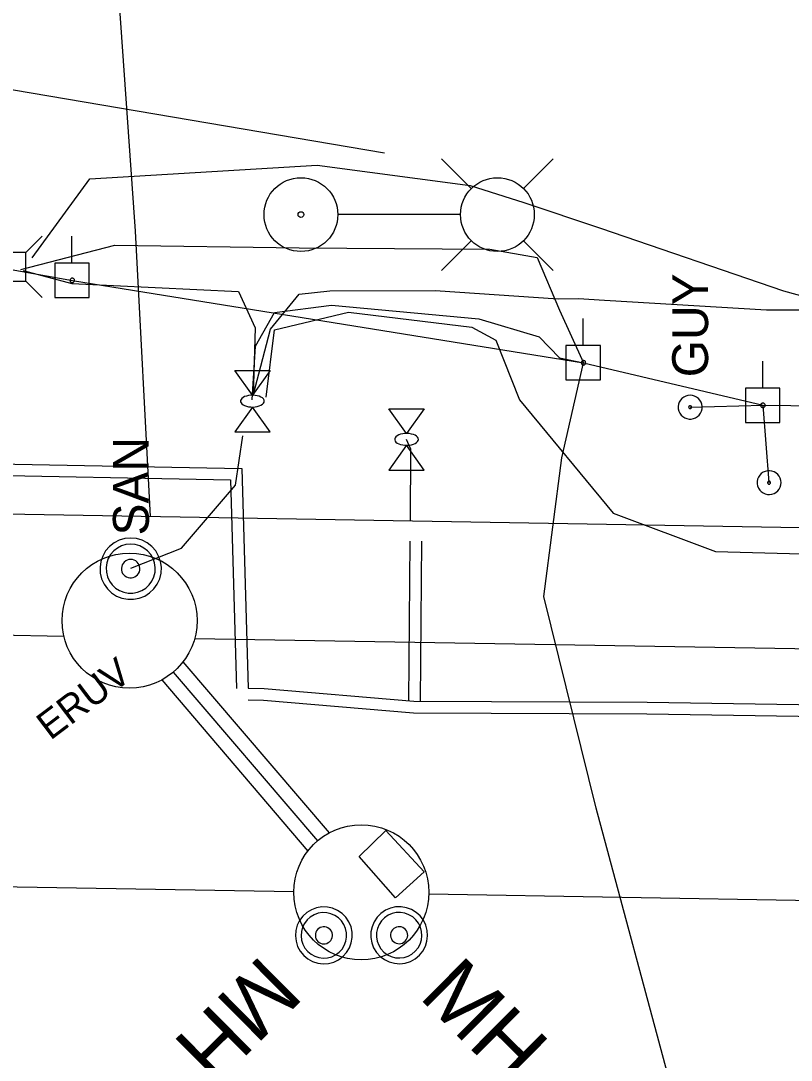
# Model space of a CAD drawing. Extents: x 596028 to 606371, y 330010 to 403088.
# Drawn here: x 604635.9 to 604718.6, y 337984.6 to 338096.2 of the extents above; entities that cross this region are included whole.
import ezdxf

# ---------------------------------------------------------------- set-up
doc = ezdxf.new("R2010")
doc.units = 0
for name, color, linetype in [('E_LTG', 7, 'Continuous'), ('E_UTL_E_Bold', 7, 'Continuous'), ('E_UTL_E_UG', 7, 'Continuous'), ('E_UTL_EGuyWire', 7, 'Continuous'), ('E_UTL_EPowerPole', 7, 'Continuous'), ('E_UTL_G_UG', 7, 'Continuous'), ('E_UTL_Overhead', 7, 'Continuous'), ('E_UTL_SAN', 7, 'Continuous'), ('E_UTL_SAN_MH', 7, 'Continuous'), ('E_UTL_SAN_UG_MMSD', 7, 'Continuous'), ('E_UTL_SAN_UG_OUTER_LIMITS', 7, 'Continuous'), ('E_UTL_T', 7, 'Continuous'), ('E_UTL_T_UG', 7, 'Continuous'), ('E_UTL_TV_UG', 7, 'Continuous')]:
    doc.layers.add(name, color=color, linetype=linetype)

# ---------------------------------------------------------------- blocks, each defined once
blk = doc.blocks.new('ACAD_PROXY_ENTITY_20')
at = {"layer": 'E_UTL_SAN'}
for points in [[(1843060.22, 1030211.23), (1843061.35, 1030212.59), (1843062.2, 1030214.15), (1843062.74, 1030215.83), (1843062.95, 1030217.59), (1843062.82, 1030219.36), (1843062.36, 1030221.07), (1843061.59, 1030222.66), (1843060.53, 1030224.08), (1843059.22, 1030225.27), (1843057.71, 1030226.19), (1843056.05, 1030226.81), (1843054.3, 1030227.1), (1843052.53, 1030227.06), (1843050.8, 1030226.68), (1843049.17, 1030225.99), (1843047.71, 1030224.99), (1843046.45, 1030223.74), (1843045.46, 1030222.28), (1843044.77, 1030220.65), (1843044.39, 1030218.92), (1843044.35, 1030217.15), (1843044.64, 1030215.4), (1843045.26, 1030213.74), (1843046.18, 1030212.23), (1843047.37, 1030210.92), (1843048.79, 1030209.86), (1843050.38, 1030209.09), (1843052.09, 1030208.63), (1843053.86, 1030208.5), (1843055.62, 1030208.71), (1843057.3, 1030209.25), (1843058.86, 1030210.1), (1843060.22, 1030211.23)], [(1843058.9, 1030212.54), (1843059.81, 1030213.64), (1843060.49, 1030214.88), (1843060.92, 1030216.23), (1843061.08, 1030217.63), (1843060.98, 1030219.05), (1843060.62, 1030220.42), (1843060, 1030221.69), (1843059.15, 1030222.82), (1843058.1, 1030223.78), (1843056.89, 1030224.51), (1843055.56, 1030225.01), (1843054.17, 1030225.24), (1843052.75, 1030225.21), (1843051.37, 1030224.91), (1843050.07, 1030224.35), (1843048.89, 1030223.56), (1843047.89, 1030222.56), (1843047.1, 1030221.38), (1843046.54, 1030220.08), (1843046.24, 1030218.7), (1843046.2, 1030217.28), (1843046.44, 1030215.88), (1843046.93, 1030214.56), (1843047.67, 1030213.35), (1843048.62, 1030212.3), (1843049.76, 1030211.45), (1843051.03, 1030210.83), (1843052.4, 1030210.46), (1843053.81, 1030210.36), (1843055.22, 1030210.53), (1843056.57, 1030210.96), (1843057.81, 1030211.64), (1843058.9, 1030212.54)], [(1843055.61, 1030215.84), (1843055.95, 1030216.25), (1843056.2, 1030216.71), (1843056.37, 1030217.22), (1843056.43, 1030217.75), (1843056.39, 1030218.28), (1843056.25, 1030218.79), (1843056.02, 1030219.27), (1843055.7, 1030219.69), (1843055.31, 1030220.05), (1843054.86, 1030220.33), (1843054.36, 1030220.51), (1843053.84, 1030220.6), (1843053.3, 1030220.59), (1843052.79, 1030220.47), (1843052.3, 1030220.26), (1843051.86, 1030219.97), (1843051.48, 1030219.59), (1843051.18, 1030219.15), (1843050.97, 1030218.66), (1843050.86, 1030218.14), (1843050.85, 1030217.61), (1843050.94, 1030217.09), (1843051.12, 1030216.59), (1843051.4, 1030216.14), (1843051.76, 1030215.74), (1843052.18, 1030215.43), (1843052.66, 1030215.19), (1843053.17, 1030215.06), (1843053.7, 1030215.02), (1843054.23, 1030215.08), (1843054.74, 1030215.24), (1843055.2, 1030215.5), (1843055.61, 1030215.84)]]:
    blk.add_lwpolyline(points, dxfattribs=at)
blk.add_text('MH', height=20.117, rotation=315, dxfattribs=at).set_placement((1843059.69, 1030197.53))

msp = doc.modelspace()

# ---------------------------------------------------------------- linework, layer by layer
at = {"layer": 'E_LTG'}
for points in [[(604684.27, 338078.14), (604681.04, 338081.36)], [(604689.81, 338078.14), (604693.04, 338081.36)], [(604683.02, 338075.36), (604669.97, 338075.36)], [(604684.27, 338072.59), (604681.04, 338069.36)], [(604689.81, 338072.59), (604693.04, 338069.36)]]:
    msp.add_lwpolyline(points, dxfattribs=at)
for centre, radius in [((604665.94, 338075.36), 3.96), ((604687.04, 338075.36), 3.96), ((604665.94, 338075.36), 0.303)]:
    msp.add_circle(centre, radius, dxfattribs=at)
at = {"layer": 'E_UTL_E_Bold'}
for points in [[(604658.83, 338058.63), (604662.64, 338058.63)], [(604660.73, 338055.97), (604658.83, 338058.63)], [(604662.64, 338058.63), (604660.73, 338055.97)], [(604662, 338055.33), (604661.98, 338055.45), (604661.91, 338055.57), (604661.8, 338055.68), (604661.65, 338055.77), (604661.47, 338055.85), (604661.26, 338055.91), (604661.03, 338055.95), (604660.79, 338055.97), (604660.55, 338055.96), (604660.32, 338055.93), (604660.1, 338055.88), (604659.9, 338055.81), (604659.73, 338055.73), (604659.6, 338055.62), (604659.51, 338055.51), (604659.47, 338055.39), (604659.47, 338055.27), (604659.51, 338055.15), (604659.6, 338055.04), (604659.73, 338054.94), (604659.9, 338054.85), (604660.1, 338054.78), (604660.32, 338054.73), (604660.55, 338054.71), (604660.79, 338054.7), (604661.03, 338054.72), (604661.26, 338054.76), (604661.47, 338054.82), (604661.65, 338054.9), (604661.8, 338054.99), (604661.91, 338055.1), (604661.98, 338055.21), (604662, 338055.33)], [(604660.73, 338054.7), (604658.83, 338052.03)], [(604662.64, 338052.03), (604660.73, 338054.7)], [(604675.38, 338054.52), (604679.19, 338054.52)], [(604677.28, 338051.86), (604675.38, 338054.52)], [(604679.19, 338054.52), (604677.28, 338051.86)], [(604658.83, 338052.03), (604662.64, 338052.03)], [(604678.55, 338051.22), (604678.53, 338051.34), (604678.46, 338051.46), (604678.35, 338051.57), (604678.2, 338051.66), (604678.02, 338051.74), (604677.81, 338051.8), (604677.58, 338051.84), (604677.34, 338051.86), (604677.1, 338051.85), (604676.87, 338051.82), (604676.65, 338051.77), (604676.45, 338051.7), (604676.28, 338051.62), (604676.15, 338051.51), (604676.06, 338051.4), (604676.02, 338051.28), (604676.02, 338051.16), (604676.06, 338051.04), (604676.15, 338050.93), (604676.28, 338050.83), (604676.45, 338050.74), (604676.65, 338050.67), (604676.87, 338050.62), (604677.1, 338050.6), (604677.34, 338050.59), (604677.58, 338050.61), (604677.81, 338050.65), (604678.02, 338050.71), (604678.2, 338050.79), (604678.35, 338050.88), (604678.46, 338050.99), (604678.53, 338051.1), (604678.55, 338051.22)], [(604677.28, 338050.59), (604675.38, 338047.92)], [(604679.19, 338047.92), (604677.28, 338050.59)], [(604675.38, 338047.92), (604679.19, 338047.92)]]:
    msp.add_lwpolyline(points, dxfattribs=at)
at = {"layer": 'E_UTL_E_UG'}
for points in [[(604660.72, 338055.46), (604661.08, 338061.22), (604663.11, 338064.85), (604669.23, 338065.65), (604685.06, 338064.18), (604691.54, 338062.22), (604693.7, 338059.99), (604696.28, 338059.45)], [(604662.22, 338055.75), (604663.09, 338063), (604671.04, 338064.89), (604684.3, 338063.27), (604686.86, 338061.88), (604689.41, 338055.47), (604699.48, 338043.29), (604710.45, 338039.19), (604734.3, 338038.53), (604754.99, 338038.72), (604761.59, 338037.72), (604765.35, 338034.35), (604765.35, 338034.35), (604765.57, 338011.48), (604764.97, 337999.85)], [(604647.68, 338037.38), (604653.11, 338039.56), (604658.91, 338046.32), (604659.69, 338051.59)]]:
    msp.add_lwpolyline(points, dxfattribs=at)
at = {"layer": 'E_UTL_EGuyWire'}
for p in [(604707.73, 338054.68), (604716.21, 338046.58)]:
    msp.add_line(p, (604715.56, 338054.88), dxfattribs=at)
for points in [[(604707.73, 338055.97), (604707.49, 338055.95), (604707.26, 338055.88), (604707.04, 338055.76), (604706.85, 338055.61), (604706.69, 338055.43), (604706.57, 338055.22), (604706.49, 338054.99), (604706.45, 338054.75), (604706.46, 338054.5), (604706.52, 338054.27), (604706.62, 338054.04), (604706.77, 338053.84), (604706.94, 338053.68), (604707.15, 338053.54), (604707.37, 338053.45), (604707.61, 338053.41), (604707.86, 338053.41), (604708.1, 338053.45), (604708.32, 338053.54), (604708.53, 338053.68), (604708.7, 338053.84), (604708.85, 338054.04), (604708.95, 338054.27), (604709.01, 338054.5), (604709.02, 338054.75), (604708.98, 338054.99), (604708.9, 338055.22), (604708.78, 338055.43), (604708.62, 338055.61), (604708.43, 338055.76), (604708.21, 338055.88), (604707.98, 338055.95), (604707.73, 338055.97)], [(604707.73, 338054.85), (604707.7, 338054.84), (604707.68, 338054.83), (604707.65, 338054.82), (604707.62, 338054.8), (604707.6, 338054.78), (604707.59, 338054.75), (604707.58, 338054.72), (604707.57, 338054.69), (604707.58, 338054.66), (604707.58, 338054.63), (604707.6, 338054.6), (604707.61, 338054.58), (604707.64, 338054.56), (604707.66, 338054.54), (604707.69, 338054.53), (604707.72, 338054.53), (604707.75, 338054.53), (604707.78, 338054.53), (604707.81, 338054.54), (604707.83, 338054.56), (604707.86, 338054.58), (604707.87, 338054.6), (604707.89, 338054.63), (604707.89, 338054.66), (604707.9, 338054.69), (604707.89, 338054.72), (604707.88, 338054.75), (604707.87, 338054.78), (604707.85, 338054.8), (604707.82, 338054.82), (604707.79, 338054.83), (604707.77, 338054.84), (604707.73, 338054.85)], [(604717.49, 338046.58), (604717.47, 338046.82), (604717.4, 338047.05), (604717.29, 338047.27), (604717.14, 338047.46), (604716.95, 338047.62), (604716.74, 338047.74), (604716.51, 338047.82), (604716.27, 338047.86), (604716.03, 338047.85), (604715.79, 338047.79), (604715.57, 338047.69), (604715.37, 338047.55), (604715.2, 338047.37), (604715.07, 338047.17), (604714.98, 338046.94), (604714.93, 338046.7), (604714.93, 338046.46), (604714.98, 338046.22), (604715.07, 338045.99), (604715.2, 338045.78), (604715.37, 338045.61), (604715.57, 338045.47), (604715.79, 338045.36), (604716.03, 338045.31), (604716.27, 338045.3), (604716.51, 338045.33), (604716.74, 338045.41), (604716.95, 338045.53), (604717.14, 338045.69), (604717.29, 338045.88), (604717.4, 338046.1), (604717.47, 338046.33), (604717.49, 338046.58)], [(604716.37, 338046.58), (604716.37, 338046.61), (604716.36, 338046.64), (604716.34, 338046.66), (604716.33, 338046.69), (604716.3, 338046.71), (604716.28, 338046.72), (604716.25, 338046.73), (604716.22, 338046.74), (604716.19, 338046.74), (604716.16, 338046.73), (604716.13, 338046.72), (604716.1, 338046.7), (604716.08, 338046.68), (604716.07, 338046.65), (604716.06, 338046.62), (604716.05, 338046.59), (604716.05, 338046.56), (604716.06, 338046.53), (604716.07, 338046.5), (604716.08, 338046.48), (604716.1, 338046.46), (604716.13, 338046.44), (604716.16, 338046.43), (604716.19, 338046.42), (604716.22, 338046.42), (604716.25, 338046.42), (604716.28, 338046.43), (604716.3, 338046.45), (604716.33, 338046.47), (604716.34, 338046.49), (604716.36, 338046.52), (604716.37, 338046.55), (604716.37, 338046.58)]]:
    msp.add_lwpolyline(points, dxfattribs=at)
at = {"layer": 'E_UTL_EPowerPole'}
for points in [[(604641.36, 338070.14), (604641.36, 338073.04)], [(604643.21, 338070.14), (604639.52, 338070.14)], [(604639.52, 338070.14), (604639.52, 338066.44)], [(604643.21, 338066.44), (604643.21, 338070.14)], [(604641.63, 338068.29), (604641.63, 338068.34), (604641.62, 338068.38), (604641.6, 338068.42), (604641.57, 338068.46), (604641.53, 338068.49), (604641.49, 338068.51), (604641.45, 338068.52), (604641.41, 338068.53), (604641.36, 338068.53), (604641.32, 338068.52), (604641.28, 338068.5), (604641.24, 338068.47), (604641.21, 338068.44), (604641.18, 338068.4), (604641.17, 338068.36), (604641.16, 338068.32), (604641.16, 338068.27), (604641.17, 338068.23), (604641.18, 338068.18), (604641.21, 338068.15), (604641.24, 338068.11), (604641.28, 338068.09), (604641.32, 338068.07), (604641.36, 338068.06), (604641.41, 338068.05), (604641.45, 338068.06), (604641.49, 338068.08), (604641.53, 338068.1), (604641.57, 338068.13), (604641.6, 338068.16), (604641.62, 338068.2), (604641.63, 338068.25), (604641.63, 338068.29)], [(604639.52, 338066.44), (604643.21, 338066.44)], [(604696.25, 338061.29), (604696.25, 338064.2)], [(604698.09, 338061.29), (604694.4, 338061.29)], [(604694.4, 338061.29), (604694.4, 338057.6)], [(604698.09, 338057.6), (604698.09, 338061.29)], [(604696.52, 338059.45), (604696.51, 338059.5), (604696.5, 338059.54), (604696.48, 338059.58), (604696.45, 338059.61), (604696.42, 338059.64), (604696.38, 338059.67), (604696.33, 338059.68), (604696.29, 338059.69), (604696.24, 338059.69), (604696.2, 338059.68), (604696.16, 338059.66), (604696.12, 338059.63), (604696.09, 338059.6), (604696.07, 338059.56), (604696.05, 338059.52), (604696.04, 338059.47), (604696.04, 338059.43), (604696.05, 338059.38), (604696.07, 338059.34), (604696.09, 338059.3), (604696.12, 338059.27), (604696.16, 338059.24), (604696.2, 338059.22), (604696.24, 338059.21), (604696.29, 338059.21), (604696.33, 338059.22), (604696.38, 338059.23), (604696.42, 338059.26), (604696.45, 338059.29), (604696.48, 338059.32), (604696.5, 338059.36), (604696.51, 338059.4), (604696.52, 338059.45)], [(604715.52, 338056.72), (604715.52, 338059.63)], [(604694.4, 338057.6), (604698.09, 338057.6)], [(604717.37, 338056.72), (604713.68, 338056.72)], [(604713.68, 338056.72), (604713.68, 338053.03)], [(604717.37, 338053.03), (604717.37, 338056.72)], [(604715.79, 338054.88), (604715.79, 338054.92), (604715.78, 338054.97), (604715.76, 338055.01), (604715.73, 338055.04), (604715.69, 338055.07), (604715.65, 338055.1), (604715.61, 338055.11), (604715.57, 338055.12), (604715.52, 338055.12), (604715.48, 338055.1), (604715.44, 338055.09), (604715.4, 338055.06), (604715.37, 338055.03), (604715.34, 338054.99), (604715.33, 338054.95), (604715.32, 338054.9), (604715.32, 338054.86), (604715.33, 338054.81), (604715.34, 338054.77), (604715.37, 338054.73), (604715.4, 338054.7), (604715.44, 338054.67), (604715.48, 338054.65), (604715.52, 338054.64), (604715.57, 338054.64), (604715.61, 338054.65), (604715.65, 338054.66), (604715.69, 338054.68), (604715.73, 338054.71), (604715.76, 338054.75), (604715.78, 338054.79), (604715.79, 338054.83), (604715.79, 338054.88)], [(604713.68, 338053.03), (604717.37, 338053.03)]]:
    msp.add_lwpolyline(points, dxfattribs=at)
at = {"layer": 'E_UTL_G_UG'}
msp.add_line((604678.79, 338023.12), (604678.92, 338040.29), dxfattribs=at)
for points in [[(604649.78, 338042.95), (604648.19, 338073.59), (604646.14, 338102.57), (604646.77, 338128.75)], [(604592.86, 338025.1), (604605.4, 338024.88), (604620.94, 338024.97), (604627.53, 338024.88), (604627.66, 338048.71), (604659.6, 338048.1), (604660.29, 338024.5), (604661.98, 338024.48), (604678.08, 338023.1), (604703.11, 338023.01), (604728.65, 338022.61), (604754.62, 338022.17), (604788.4, 338021.61), (604836.01, 338021.58), (604864.95, 338021.48), (604896.37, 338021.5), (604900.27, 338026.31), (604935.52, 338026.84), (604967.49, 338026.3), (604985, 338025.85), (604984.37, 338049.04), (604985.32, 338080.05), (604985.44, 338110.91)], [(604677.69, 338042.47), (604677.75, 338050.18), (604677.28, 338051.22)], [(604628.78, 338024.89), (604628.9, 338047.44), (604658.38, 338046.87), (604659.04, 338024.47)], [(604632.12, 338043.25), (604936.03, 338038.05), (604984.53, 338043.23)], [(604677.54, 338023.13), (604677.67, 338040.3)], [(604660.28, 338023.25), (604661.92, 338023.23), (604678.02, 338021.85), (604703.1, 338021.76), (604728.63, 338021.36), (604754.6, 338020.92), (604788.39, 338020.36), (604836.01, 338020.33), (604864.95, 338020.23), (604896.97, 338020.25), (604900.87, 338025.07), (604935.52, 338025.59), (604967.46, 338025.05), (604984.97, 338024.6)]]:
    msp.add_lwpolyline(points, dxfattribs=at)
at = {"layer": 'E_UTL_Overhead'}
msp.add_lwpolyline([(604103.64, 338065.21), (604129.71, 338064.26), (604269.62, 338062.62), (604344.53, 338119.28), (604560.83, 338082.73), (604641.4, 338068.29), (604696.28, 338059.45), (604715.56, 338054.88), (604786.57, 338054.03), (604829.08, 338053.72), (604872.92, 338052.19), (604977.47, 338050.01), (605123.72, 338048.42), (605215.39, 338038.9)], dxfattribs=at)
at = {"layer": 'E_UTL_SAN_MH'}
for points in [[(604647.66, 338040.63), (604647.04, 338040.57), (604646.44, 338040.4), (604645.88, 338040.11), (604645.38, 338039.72), (604644.97, 338039.25), (604644.66, 338038.7), (604644.45, 338038.11), (604644.37, 338037.49), (604644.4, 338036.86), (604644.54, 338036.25), (604644.8, 338035.68), (604645.17, 338035.17), (604645.62, 338034.74), (604646.15, 338034.4), (604646.73, 338034.17), (604647.35, 338034.05), (604647.98, 338034.05), (604648.59, 338034.17), (604649.17, 338034.4), (604649.7, 338034.74), (604650.16, 338035.17), (604650.52, 338035.68), (604650.78, 338036.25), (604650.93, 338036.86), (604650.96, 338037.49), (604650.87, 338038.11), (604650.66, 338038.7), (604650.35, 338039.25), (604649.94, 338039.72), (604649.45, 338040.11), (604648.89, 338040.4), (604648.29, 338040.57), (604647.66, 338040.63)], [(604647.66, 338039.97), (604647.16, 338039.93), (604646.68, 338039.78), (604646.23, 338039.55), (604645.84, 338039.24), (604645.51, 338038.86), (604645.26, 338038.43), (604645.1, 338037.96), (604645.02, 338037.46), (604645.05, 338036.96), (604645.17, 338036.47), (604645.38, 338036.01), (604645.67, 338035.6), (604646.03, 338035.26), (604646.45, 338034.99), (604646.92, 338034.8), (604647.41, 338034.71), (604647.91, 338034.71), (604648.41, 338034.8), (604648.87, 338034.99), (604649.29, 338035.26), (604649.66, 338035.6), (604649.95, 338036.01), (604650.16, 338036.47), (604650.28, 338036.96), (604650.3, 338037.46), (604650.23, 338037.96), (604650.06, 338038.43), (604649.81, 338038.86), (604649.48, 338039.24), (604649.09, 338039.55), (604648.64, 338039.78), (604648.16, 338039.93), (604647.66, 338039.97)], [(604647.66, 338038.32), (604647.47, 338038.31), (604647.29, 338038.25), (604647.13, 338038.17), (604646.98, 338038.05), (604646.86, 338037.91), (604646.76, 338037.74), (604646.7, 338037.57), (604646.67, 338037.38), (604646.68, 338037.19), (604646.73, 338037.01), (604646.8, 338036.84), (604646.91, 338036.69), (604647.05, 338036.56), (604647.21, 338036.45), (604647.38, 338036.38), (604647.57, 338036.35), (604647.76, 338036.35), (604647.94, 338036.38), (604648.12, 338036.45), (604648.27, 338036.56), (604648.41, 338036.69), (604648.52, 338036.84), (604648.6, 338037.01), (604648.64, 338037.19), (604648.65, 338037.38), (604648.62, 338037.57), (604648.56, 338037.74), (604648.47, 338037.91), (604648.35, 338038.05), (604648.2, 338038.17), (604648.03, 338038.25), (604647.85, 338038.31), (604647.66, 338038.32)]]:
    msp.add_lwpolyline(points, dxfattribs=at)
msp.add_lwpolyline([(604672.19, 338006.42), (604675.06, 338009.22), (604679.18, 338004.78), (604676.1, 338002)], close=True, dxfattribs=at)
for centre in [(604647.54, 338031.76), (604672.42, 338002.59)]:
    msp.add_circle(centre, 7.25, dxfattribs=at)
at = {"layer": 'E_UTL_SAN_UG_MMSD'}
for p, q in [((604202.07, 338037.6), (604640.48, 338030.1)), ((604654.54, 338029.86), (605016.26, 338023.68)), ((603897.65, 338015.8), (604665.17, 338002.68)), ((604679.67, 338002.43), (605085.21, 337995.5))]:
    msp.add_line(p, q, dxfattribs=at)
msp.add_lwpolyline([(604652.24, 338026.24), (604667.71, 338008.11)], dxfattribs=at)
at = {"layer": 'E_UTL_SAN_UG_OUTER_LIMITS'}
for p, q in [((604653.28, 338027.34), (604668.96, 338008.96)), ((604651, 338025.39), (604666.68, 338007.01))]:
    msp.add_line(p, q, dxfattribs=at)
at = {"layer": 'E_UTL_T'}
for points in [[(604636.41, 338071.3), (604638.16, 338073.05)], [(604636.41, 338071.3), (604633.31, 338071.3)], [(604636.41, 338068.2), (604636.41, 338071.3)], [(604633.31, 338068.2), (604636.41, 338068.2)], [(604636.41, 338068.2), (604638.16, 338066.45)]]:
    msp.add_lwpolyline(points, dxfattribs=at)
at = {"layer": 'E_UTL_T_UG'}
for points in [[(604565.56, 338094.25), (604582.26, 338091.62), (604629.37, 338089.71), (604674.9, 338081.98)], [(604637.08, 338070.72), (604643.27, 338079.21), (604667.67, 338080.67)], [(604667.67, 338080.67), (604684.12, 338078.5), (604689.86, 338076.65), (604698.09, 338073.92)], [(604698.09, 338073.92), (604717.74, 338067.17), (604737.51, 338061.73)], [(604635.88, 338069.46), (604645.97, 338072.07), (604665.75, 338071.79), (604675.98, 338071.72), (604686.22, 338071.65), (604691.3, 338070.77), (604693.7, 338065.09), (604696.28, 338059.45)], [(604636.13, 338069.34), (604641.36, 338067.97), (604659.25, 338067.1), (604661.02, 338063.19), (604660.82, 338055.93)], [(604660.82, 338055.93), (604662.69, 338063.07), (604665.74, 338066.8), (604669.04, 338067.16), (604680.37, 338067.2), (604693.58, 338066.32), (604695.75, 338066.34), (604698.55, 338066.18), (604715.92, 338065.12), (604735.94, 338065.15), (604782.95, 338064.26), (604788.76, 338058.92), (604788.56, 338049.2), (604789.03, 338031.15), (604789.95, 338010), (604790.25, 337998.23), (604788.6, 337987.22), (604786.82, 337977.93)]]:
    msp.add_lwpolyline(points, dxfattribs=at)
at = {"layer": 'E_UTL_TV_UG'}
msp.add_lwpolyline([(604705.75, 337981.43), (604697.65, 338011.62), (604692.01, 338034.37), (604693.94, 338049.23), (604696.28, 338059.45)], dxfattribs=at)

# ---------------------------------------------------------------- block references
at = {"layer": 'E_UTL_SAN_MH', "yscale": 0.32808333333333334}
for p, xscale, rotation in [((269289.94, 944129.58), 0.3280833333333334, -90.24784722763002), ((1563.7, -2779.38), 0.32808333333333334, 0.2637645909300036)]:
    msp.add_blockref('ACAD_PROXY_ENTITY_20', p, dxfattribs=dict(at, xscale=xscale, rotation=rotation))

# ---------------------------------------------------------------- texts
at = {"layer": 'E_UTL_EGuyWire'}
msp.add_text('GUY', height=3.85, rotation=90, dxfattribs=at).set_placement((604709.66, 338057.89))
at = {"layer": 'E_UTL_Overhead'}
msp.add_text('ERUV', height=3, rotation=37.1063, dxfattribs=at).set_placement((604639.04, 338018.85))
at = {"layer": 'E_UTL_SAN_MH'}
msp.add_text('SAN', height=3.849, rotation=90, dxfattribs=at).set_placement((604649.61, 338040.9))

doc.saveas('drawing.dxf')
